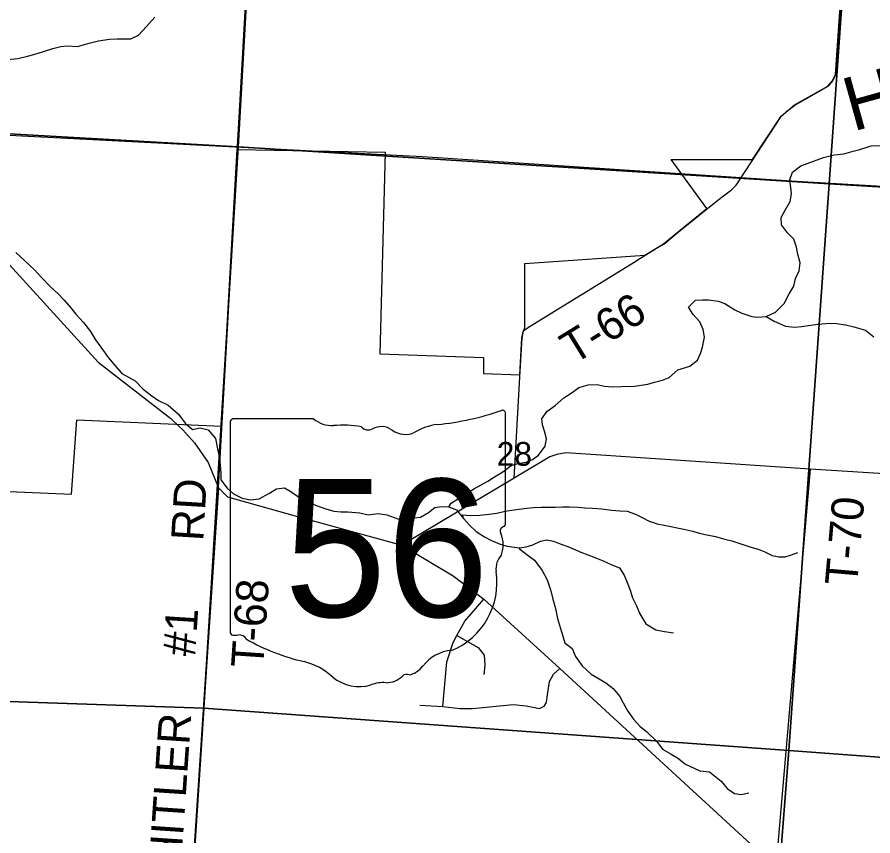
# Model space of a CAD drawing. Extents: x 0 to 42.5, y 0 to 22.
# Drawn here: x 3.26 to 4.014, y 19.377 to 20.099 of the extents above; entities that cross this region are included whole.
import ezdxf

# ---------------------------------------------------------------- set-up
doc = ezdxf.new("R2010")
doc.units = 0
for name, color, linetype in [('Default', 7, 'Continuous'), ('GM_X_County_Road', 7, 'Continuous'), ('GM_X_Interchange_Ramps', 7, 'Continuous'), ('GM_X_Minor_River', 7, 'Continuous'), ('GM_X_Minor_River_Text', 7, 'Continuous'), ('GM_X_Rail_Line', 7, 'Continuous'), ('GM_X_Section', 7, 'Continuous'), ('GM_X_Section_Text', 7, 'Continuous'), ('GM_X_State_Location', 7, 'Continuous'), ('GM_X_State_Route', 7, 'Continuous'), ('GM_X_State_Shield', 7, 'Continuous'), ('GM_X_Township_Road', 7, 'Continuous'), ('GM_X_Township_Road_Text', 7, 'Continuous')]:
    doc.layers.add(name, color=color, linetype=linetype)

msp = doc.modelspace()

# ---------------------------------------------------------------- linework, layer by layer
at = {"layer": 'Default'}
msp.add_lwpolyline([(3.17698, 19.68401), (3.30774, 19.67848), (3.31248, 19.74423), (3.43993, 19.73843), (3.45378, 19.98244), (3.58444, 19.98016), (3.57973, 19.80231), (3.67095, 19.79912), (3.67095, 19.78492), (3.70303, 19.78379), (3.70488, 19.81646), (3.70625, 19.8229), (3.70746, 19.82506), (3.70747, 19.88197), (3.81327, 19.88937), (3.82988, 19.89915), (3.84283, 19.91025), (3.86795, 19.9304), (3.83653, 19.97365), (3.90821, 19.97365), (3.9335, 20.01182), (3.94531, 20.02178), (3.97478, 20.03844), (3.9786, 20.04277), (3.98148, 20.04863), (3.99204, 20.20267)], dxfattribs=at)
at = {"layer": 'GM_X_County_Road'}
for points in [[(3.95904, 19.70046), (3.74347, 19.7151), (3.73569, 19.71345), (3.72943, 19.7116), (3.69801, 19.6928), (3.59905, 19.63357)], [(4.55979, 19.69172), (4.5089, 19.66909), (4.50055, 19.66669), (4.32613, 19.67757), (4.30419, 19.67894), (4.28243, 19.68029), (3.95904, 19.70046)]]:
    msp.add_lwpolyline(points, dxfattribs=at)
at = {"layer": 'GM_X_Interchange_Ramps'}
for points in [[(3.11995, 19.00104), (3.37078, 18.98615), (3.37742, 18.98467), (3.39197, 18.98393), (3.40756, 19.23914), (3.43715, 19.68433), (3.46832, 20.23391), (3.46843, 20.23651), (3.47315, 20.34124), (3.47328, 20.34399), (3.48511, 20.52333), (3.49253, 20.65067), (3.50401, 20.9), (2.3057, 20.9)], [(5.48884, 19.405), (5.50057, 19.55251), (5.51061, 19.66936), (5.5156, 19.73605), (5.52526, 19.85376), (5.53536, 19.98472), (5.54606, 20.11658), (5.56474, 20.34561), (5.56563, 20.35496), (5.56586, 20.35729), (5.60252, 20.8068), (5.60957, 20.9), (3.50401, 20.9), (3.49253, 20.65067), (3.48511, 20.52333), (3.47328, 20.34399), (3.47315, 20.34124), (3.46843, 20.23651), (3.46832, 20.23391), (3.43715, 19.68433), (3.40756, 19.23914)]]:
    msp.add_lwpolyline(points, dxfattribs=at)
at = {"layer": 'GM_X_Minor_River'}
for points in [[(3.25123, 20.06172), (3.26034, 20.06281), (3.26887, 20.06484), (3.27438, 20.06614), (3.28292, 20.06893), (3.29127, 20.07154), (3.2983, 20.0732), (3.3038, 20.07393), (3.31289, 20.0733), (3.32333, 20.07627), (3.33168, 20.07831), (3.34116, 20.07977), (3.34798, 20.08011), (3.36011, 20.08003), (3.36677, 20.08341), (3.37382, 20.09096), (3.38107, 20.09928)], [(3.6405, 19.66735), (3.64242, 19.67057), (3.64984, 19.67546), (3.65707, 19.68017), (3.66315, 19.68355), (3.66885, 19.68674), (3.67475, 19.69013), (3.68065, 19.69389), (3.68806, 19.69821), (3.69549, 19.70387), (3.70156, 19.70554), (3.70858, 19.70682), (3.71409, 19.70926), (3.71961, 19.71302), (3.72534, 19.72078), (3.72652, 19.72742), (3.72485, 19.73408), (3.72299, 19.73961), (3.72245, 19.74512), (3.72685, 19.75156), (3.73408, 19.75683), (3.74189, 19.76362), (3.74931, 19.76833), (3.75521, 19.77266), (3.76337, 19.77508), (3.77114, 19.77522), (3.77777, 19.77365), (3.78477, 19.77323), (3.79235, 19.77337), (3.8041, 19.77387), (3.81017, 19.77459), (3.81586, 19.77569), (3.82194, 19.77717), (3.82877, 19.77903), (3.83466, 19.78146), (3.84247, 19.78806), (3.85291, 19.79142), (3.85957, 19.79669), (3.86245, 19.80257), (3.86419, 19.80826), (3.86576, 19.81699), (3.86466, 19.82384), (3.86167, 19.83051), (3.85603, 19.83701), (3.8519, 19.8435), (3.85781, 19.84954), (3.86406, 19.84988), (3.86956, 19.84984), (3.87789, 19.84865), (3.88394, 19.84671), (3.89262, 19.84114), (3.89867, 19.83806), (3.90755, 19.83516), (3.91305, 19.83474), (3.92025, 19.83507), (3.92842, 19.83901), (3.93605, 19.84676), (3.94064, 19.85528), (3.94467, 19.86209), (3.94622, 19.86873), (3.94948, 19.87537), (3.95028, 19.88258), (3.94806, 19.8902), (3.94696, 19.89629), (3.94473, 19.90352), (3.93908, 19.90907), (3.93381, 19.91595), (3.93347, 19.92241), (3.93692, 19.92885), (3.94133, 19.93661), (3.94251, 19.94345), (3.94197, 19.94896), (3.94126, 19.95581), (3.94338, 19.96244), (3.9508, 19.9681), (3.95631, 19.97015), (3.97093, 19.97538), (3.98023, 19.97779), (3.98876, 19.97869), (3.99693, 19.98111), (4.00281, 19.98259), (4.01287, 19.98556), (4.02083, 19.98608)], [(3.25872, 19.89159), (3.26664, 19.88431), (3.27512, 19.87628), (3.28152, 19.86921), (3.28886, 19.86175), (3.29583, 19.85524), (3.30129, 19.8495), (3.30713, 19.84281), (3.31164, 19.83727), (3.31823, 19.82982), (3.32443, 19.82199), (3.32894, 19.81455), (3.33589, 19.80481), (3.34002, 19.79908), (3.3468, 19.79106), (3.35225, 19.78494), (3.35792, 19.78167), (3.36396, 19.7784), (3.37093, 19.77114), (3.37847, 19.7652), (3.38451, 19.76117), (3.39282, 19.75693), (3.40206, 19.74908), (3.40808, 19.74125), (3.41448, 19.73551), (3.42112, 19.73698), (3.42831, 19.73523), (3.43471, 19.72759)], [(3.92025, 19.83507), (3.92724, 19.83123), (3.93725, 19.82679), (3.9452, 19.82579), (3.95146, 19.82632), (3.95772, 19.82723), (3.96587, 19.82832), (3.97649, 19.8292), (3.98217, 19.82898), (3.99031, 19.82778), (3.9975, 19.82622), (4.0079, 19.82311), (4.01526, 19.81736)], [(3.43471, 19.72759), (3.43636, 19.71845), (3.43821, 19.71065), (3.43893, 19.7038), (3.43926, 19.69715), (3.43941, 19.69107), (3.44506, 19.68381), (3.45071, 19.67883), (3.45827, 19.67517), (3.46546, 19.6736), (3.47323, 19.67451), (3.48179, 19.67901), (3.48863, 19.68334), (3.49546, 19.68406), (3.50207, 19.6804), (3.51207, 19.67331), (3.51906, 19.67041), (3.52625, 19.6677), (3.53211, 19.66558), (3.53911, 19.66363), (3.54536, 19.66302), (3.55142, 19.66298), (3.56184, 19.66196), (3.56921, 19.6604), (3.57813, 19.66148), (3.58589, 19.66029), (3.59534, 19.65681), (3.60235, 19.65619), (3.60994, 19.65766), (3.61544, 19.6582), (3.62247, 19.66252), (3.62799, 19.66667), (3.63425, 19.66777), (3.6405, 19.66735), (3.64731, 19.66465), (3.65352, 19.65719), (3.65897, 19.65089), (3.66462, 19.64553), (3.67199, 19.64092), (3.67803, 19.63765), (3.68578, 19.63437), (3.69202, 19.63262), (3.70243, 19.63122), (3.7085, 19.63213), (3.71439, 19.63381), (3.72123, 19.63718), (3.72692, 19.63829), (3.73279, 19.63711), (3.73865, 19.63479), (3.74545, 19.63228), (3.75698, 19.62745), (3.76927, 19.62281), (3.77645, 19.61973), (3.7842, 19.61625), (3.79082, 19.61374), (3.79494, 19.60706), (3.79756, 19.60058), (3.80036, 19.59392), (3.8024, 19.58706), (3.80596, 19.58001), (3.80876, 19.57315), (3.8142, 19.56437), (3.82307, 19.55899), (3.83064, 19.55761), (3.8386, 19.55642)], [(3.65352, 19.65719), (3.6524, 19.66024), (3.65941, 19.65982), (3.66775, 19.66014), (3.6759, 19.66104), (3.68272, 19.66176), (3.69012, 19.66361), (3.69562, 19.66453), (3.70928, 19.66615), (3.71516, 19.66668), (3.72217, 19.66701), (3.72861, 19.66697), (3.73411, 19.66713), (3.74055, 19.66747), (3.74699, 19.66743), (3.75419, 19.66719), (3.76025, 19.66658), (3.76726, 19.66616), (3.77502, 19.66554), (3.78411, 19.66453), (3.79131, 19.66391), (3.79775, 19.66349), (3.80512, 19.66097), (3.81098, 19.65808), (3.81721, 19.65481), (3.82421, 19.65249), (3.83026, 19.65112), (3.84768, 19.64758), (3.85562, 19.64582), (3.8613, 19.64408), (3.86792, 19.6427), (3.87549, 19.64132), (3.88381, 19.63899), (3.88987, 19.63743), (3.89894, 19.63433), (3.90594, 19.63201), (3.91313, 19.63006), (3.91899, 19.62774), (3.9256, 19.62447), (3.93147, 19.62329), (3.93715, 19.62345), (3.94266, 19.62512), (3.94816, 19.62718)], [(3.70243, 19.63122), (3.70262, 19.63046), (3.70922, 19.62529), (3.71601, 19.62049), (3.72278, 19.61114), (3.72727, 19.60294), (3.73044, 19.59341), (3.73229, 19.58599), (3.73451, 19.5778), (3.73635, 19.56905), (3.73988, 19.55725), (3.74266, 19.54734), (3.74908, 19.54255), (3.75225, 19.53531), (3.75789, 19.52729), (3.76599, 19.51983), (3.77166, 19.51656), (3.77902, 19.51233), (3.78543, 19.50735), (3.79126, 19.50009), (3.79426, 19.49456), (3.7982, 19.48731), (3.80327, 19.48025), (3.80891, 19.47394), (3.81495, 19.46896), (3.8238, 19.46035), (3.82888, 19.45386), (3.83643, 19.44944), (3.84209, 19.44617), (3.84926, 19.44061), (3.86192, 19.43464), (3.87044, 19.43364), (3.88062, 19.42559), (3.88589, 19.41909), (3.8923, 19.41449), (3.89836, 19.41388), (3.905, 19.41517)]]:
    msp.add_lwpolyline(points, dxfattribs=at)
at = {"layer": 'GM_X_Rail_Line'}
msp.add_lwpolyline([(2.61877, 19.97568), (2.65326, 19.99211), (2.69136, 20.00655), (2.71989, 20.01446), (2.74816, 20.0195), (2.77247, 20.02118), (2.80231, 20.02106), (2.83481, 20.01941), (2.91733, 20.01403), (3.26401, 19.99461), (3.61724, 19.97619), (3.94708, 19.95463), (4.29937, 19.93411), (4.5956, 19.91226), (5.05555, 19.8842), (5.17532, 19.87894), (5.25442, 19.87492), (5.30129, 19.87455), (5.33367, 19.88019), (5.36925, 19.89196), (5.40278, 19.90809), (5.43829, 19.93181), (5.47396, 19.96523), (5.54064, 20.03224)], dxfattribs=at)
at = {"layer": 'GM_X_Section'}
for points in [[(2.97397, 20.51334), (3.48334, 20.48855), (3.4546, 19.98469), (2.94222, 20.01405)], [(3.48334, 20.48855), (4.01124, 20.45591), (3.97586, 19.95227), (3.4546, 19.98469)], [(4.01124, 20.45591), (4.52494, 20.42409), (4.48862, 19.92064), (3.97586, 19.95227)], [(3.4546, 19.98469), (3.42438, 19.48993), (2.90759, 19.50738), (2.94222, 20.01405)], [(3.4546, 19.98469), (3.97586, 19.95227), (3.94032, 19.4526), (3.42438, 19.48993)], [(3.97586, 19.95227), (4.48862, 19.92064), (4.45285, 19.41472), (3.94032, 19.4526)], [(2.90759, 19.50738), (3.42438, 19.48993), (3.39164, 18.98496), (3.36778, 18.98583), (2.87643, 19.01565)], [(3.42438, 19.48993), (3.94032, 19.4526), (3.90077, 18.94861), (3.89319, 18.94826), (3.39164, 18.98496)], [(3.94032, 19.4526), (4.45285, 19.41472), (4.41842, 18.91278), (4.41142, 18.91319), (3.90077, 18.94861)]]:
    msp.add_lwpolyline(points, close=True, dxfattribs=at)
at = {"layer": 'GM_X_State_Route'}
for points in [[(3.2105, 19.9272), (3.33138, 19.79487), (3.39532, 19.74526), (3.40258, 19.73833)], [(3.40258, 19.73833), (3.40585, 19.7352), (3.41622, 19.72391), (3.42829, 19.70642), (3.43726, 19.68407)], [(3.43726, 19.68407), (3.44516, 19.67608), (3.5071, 19.65897)], [(3.5071, 19.65897), (3.59905, 19.63357), (3.64438, 19.6067), (3.67123, 19.58594), (3.73828, 19.52485), (3.92891, 19.34957)]]:
    msp.add_lwpolyline(points, dxfattribs=at)
at = {"layer": 'GM_X_State_Shield'}
for p, q in [((3.69054, 19.65301), (3.69054, 19.74943)), ((3.44768, 19.74169), (3.44768, 19.55736)), ((3.52119, 19.74487), (3.45007, 19.74487)), ((3.69052, 19.65303), (3.69054, 19.65301))]:
    msp.add_line(p, q, dxfattribs=at)
for centre, radius, start, end in [((3.60403, 19.99617), 0.25756, 275.84447, 288.90645), ((3.68785, 19.74983), 0.0027, 351.86209, 97.738), ((3.45046, 19.74209), 0.00281, 98.1301, 188.1301), ((3.53813, 19.76627), 0.02729, 231.61951, 271.11188), ((3.54718, 19.64138), 0.09797, 80.48669, 94.98827), ((3.56942, 19.74304), 0.00787, 219.79206, 297.10237), ((3.58098, 19.72174), 0.01637, 54.46668, 119.14113), ((3.6021, 19.75096), 0.01969, 233.85621, 294.82819), ((3.63688, 19.68857), 0.05182, 97.34618, 120.76885), ((3.68992, 19.64593), 0.00418, 107.94398, 210.33697), ((3.68766, 19.65264), 0.00289, 289.60381, 7.73413), ((3.6633, 19.63374), 0.02512, 340.03296, 23.64957), ((3.70023, 19.61265), 0.01827, 136.8065, 186.92959), ((3.61846, 19.60039), 0.06442, 292.30889, 8.98584), ((3.45048, 19.55696), 0.00284, 171.95839, 258.30661), ((3.45091, 19.57582), 0.02166, 267.33899, 280.60386), ((3.45535, 19.54673), 0.00781, 29.74838, 93.27175), ((3.55396, 19.71234), 0.18599, 240.41292, 257.1985), ((3.64562, 19.50561), 0.03528, 94.40312, 142.57675), ((3.49851, 19.47455), 0.05819, 47.18416, 75.83597), ((3.60092, 19.5395), 0.02081, 282.87319, 323.27711), ((3.56145, 19.54581), 0.03693, 230.70037, 286.29184), ((3.58548, 19.53201), 0.01967, 268.77702, 315.54927), ((3.60328, 19.51416), 0.00554, 65.75173, 132.64842), ((3.58278, 19.48208), 0.03034, 85.69512, 111.20995)]:
    msp.add_arc(centre, radius, start, end, dxfattribs=at)
at = {"layer": 'GM_X_Township_Road'}
for p, q in [((3.95904, 19.70046), (3.92891, 19.34957)), ((3.43726, 19.68407), (3.40767, 19.23888))]:
    msp.add_line(p, q, dxfattribs=at)
for points in [[(3.90165, 19.96292), (3.93361, 20.01156), (3.93857, 20.01626), (3.94542, 20.02152), (3.97489, 20.03817), (3.97871, 20.04251), (3.98159, 20.04837), (3.99308, 20.20605)], [(3.89623, 19.95466), (3.90056, 19.96126), (3.90165, 19.96292)], [(3.86258, 19.92574), (3.8776, 19.93779), (3.88388, 19.94249), (3.88979, 19.947), (3.89379, 19.95095), (3.89514, 19.95301), (3.89623, 19.95466)], [(3.8066, 19.88492), (3.82257, 19.89477), (3.82999, 19.89889), (3.84294, 19.90998), (3.86104, 19.9245), (3.86258, 19.92574)], [(3.70955, 19.82495), (3.71074, 19.82582), (3.80533, 19.88414), (3.8066, 19.88492)], [(3.70307, 19.78214), (3.70499, 19.81619), (3.70636, 19.82263), (3.70875, 19.82437), (3.70955, 19.82495)], [(3.69801, 19.6928), (3.70304, 19.78164), (3.70307, 19.78214)], [(3.63502, 19.49139), (3.63882, 19.53064), (3.64418, 19.54784), (3.64761, 19.55391), (3.65469, 19.56648), (3.67123, 19.58594)], [(3.64761, 19.55391), (3.6663, 19.54333), (3.6717, 19.5366), (3.67232, 19.52767), (3.67126, 19.51952)], [(3.61476, 19.49246), (3.63502, 19.49139), (3.65016, 19.48964), (3.66135, 19.48966), (3.67634, 19.49096), (3.69703, 19.49311), (3.70877, 19.49179), (3.7203, 19.48972), (3.7245, 19.49175), (3.72644, 19.49494), (3.72708, 19.49949), (3.72917, 19.51332), (3.73287, 19.51991), (3.73828, 19.52485)]]:
    msp.add_lwpolyline(points, dxfattribs=at)

# ---------------------------------------------------------------- texts
at = {"layer": 'GM_X_Minor_River_Text'}
msp.add_text('Homing', height=0.047347, rotation=15.53186, dxfattribs=at).set_placement((3.99651, 19.99809))
at = {"layer": 'GM_X_Section_Text'}
msp.add_text('28', height=0.020928, rotation=0.00001, dxfattribs=at).set_placement((3.68266, 19.70361))
at = {"layer": 'GM_X_State_Location'}
msp.add_text('56', height=0.0000947, rotation=0.00001, dxfattribs=at).set_placement((3.50662, 19.63455))
for s in ['s', 'r']:
    msp.add_text(s, height=0.0000947, dxfattribs=at).set_placement((3.53046, 19.64144))
at = {"layer": 'GM_X_State_Shield'}
msp.add_text('56', height=0.121435, dxfattribs=at).set_placement((3.49514, 19.57036))
at = {"layer": 'GM_X_Township_Road_Text'}
for s, rotation, p in [('T-66', 31.63144, (3.75039, 19.79243)), ('RD', 86.54661, (3.42383, 19.63675)), ('T-70', 85.06076, (4.00033, 19.59725)), ('T-68', 86.11635, (3.47665, 19.52482)), ('#1', 86.30823, (3.41675, 19.53513)), ('HITLER', 86.12135, (3.40426, 19.34975))]:
    msp.add_text(s, height=0.028409, rotation=rotation, dxfattribs=at).set_placement(p)

doc.saveas('drawing.dxf')
